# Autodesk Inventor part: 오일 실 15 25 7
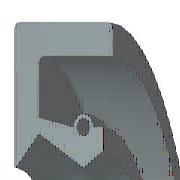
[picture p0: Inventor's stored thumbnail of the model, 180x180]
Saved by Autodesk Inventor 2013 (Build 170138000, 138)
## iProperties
Created: 2012-02
Part Number: 오일 실 15 25 7
Material: 고무
Description: 오일-실
Document SubType Name: Modeling
Standard: KS B 2804
Designer: mduedu
Standards Organization: KS
Language: ko-KR
Size Designation: D - 15 25 7
Categories: <MemberInstance><Categories><Category DisplayName="샤프트 부품" InternalName="7f7aeb1f-a693-4053-b835-cee3144e0d98" Mnemonic="SHFT"><Category DisplayName="실링" Intern
Density: 0.93 g/cm^3
IsCustomPart: 1
Author: mduedu
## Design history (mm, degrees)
revolve "본체" stored, may be unused: angle "d17" = 90 deg
revolve "스프링1" stored, may be unused: angle "d18" = 90 deg
body "Solid1"
sketch "스케치1"
  geometry: L1 (0, 12.5)-(7, 12.5); L2 (7, 10.75)-(1.75, 10.75); L3 (1.75, 9.25)-(4.9, 7.5); L4 (4.9, 7.5)-(0, 7.5); L5 (0, 0)-(9.586, 0) reference; L6 (4.9, 7.5)-(6.3, 8.375); L7 (0, 18)-(0, -3) reference; L8 (-1.941, 0)-(11.507, 0) reference; L9 (4.2, 9.6)-(1.75, 10.09); L10 (1.75, 10.09)-(1.75, 10.75); L11 (0, 12.5)-(0, 7.588); L12 (4.9, 7.5)-(0, 7.5); L13 (1.75, 9.25)-(0.152, 7.528); L14 (7, 12.5)-(7, 10.75); L15 (5.6, 9.6)-(6.3, 9.6); L16 (6.3, 9.6)-(6.3, 8.375); C1 r 0.455 at (4.9, 9.6); A1 r 0.7 centre (4.9, 9.6) between (5.6, 9.6) and (4.2, 9.6); A2 r 0.088 centre (0.088, 7.588) between (0, 7.588) and (0.152, 7.528); 1 further point
  constraints: 28 end point, 5 horizontal alignment, 5 point on line, 4 point on circle, 4 vertical alignment, 3 centre point, 3 tangent, 2 collinear, 2 horizontal, 2 perpendicular, 1 coincident, 1 parallel
  dimensions: "d0" = 25 diameter of L1 L5 (= SD2); "d1" = 1.75 distance of L1.end L2.start (= SD); "d2" = 0.91 diameter of C1 (= SPDI); "d3" = 1.4 diameter of A1 (= SPDA); "d4" = 15 diameter of L3.end L5 (= NND); "d5" = 18.5 diameter of L3.start L5 (= TKDM); "d7" = 20.18 diameter of L9.end L5 (= TKDM + 0.24 x SWDT); "d8" = 1.75 distance between parallel lines of L11 L10 (= SD); "d9" = 4.9 distance from line of L11 C1.centre (= SPDST); "d10" = 19.2 diameter of C1.centre L5 (= HLDM); "d11" = 0.0875 radius of A2 (= 0.25 x LAB); "d12" = 6.3 distance between parallel lines of L11 L16 (= SDI); "d13" = 16.75 diameter of L6.end L5 (= ABDM); "d14" = 7 distance from line of L11 L1.end (= SWDT)
fillet "모깎기1" dims "d6" = 0.3 (= RR)
other parameters: "SD2" = 25 [user parameter; used in 1 equation term], "SWDT" = 7 [user parameter; used in 2 equation terms], "RR" = 0.3 [user parameter; used in 1 equation term], "SD" = 1.75 [user parameter; used in 2 equation terms], "NND" = 15 [user parameter; used in 1 equation term], "SPDA" = 1.4 [user parameter; used in 1 equation term], "SPDI" = 0.91 [user parameter; used in 1 equation term], "TKDM" = 18.5 [user parameter; used in 2 equation terms], "HLDM" = 19.2 [user parameter; used in 1 equation term], "ABDM" = 16.75 [user parameter; used in 1 equation term], "SDI" = 6.3 [user parameter; used in 1 equation term], "SPDST" = 4.9 [user parameter; used in 1 equation term], "LAB" = 0.35 [user parameter; used in 1 equation term], "d15" = 0, "d16" = 0, "d19" = 0
